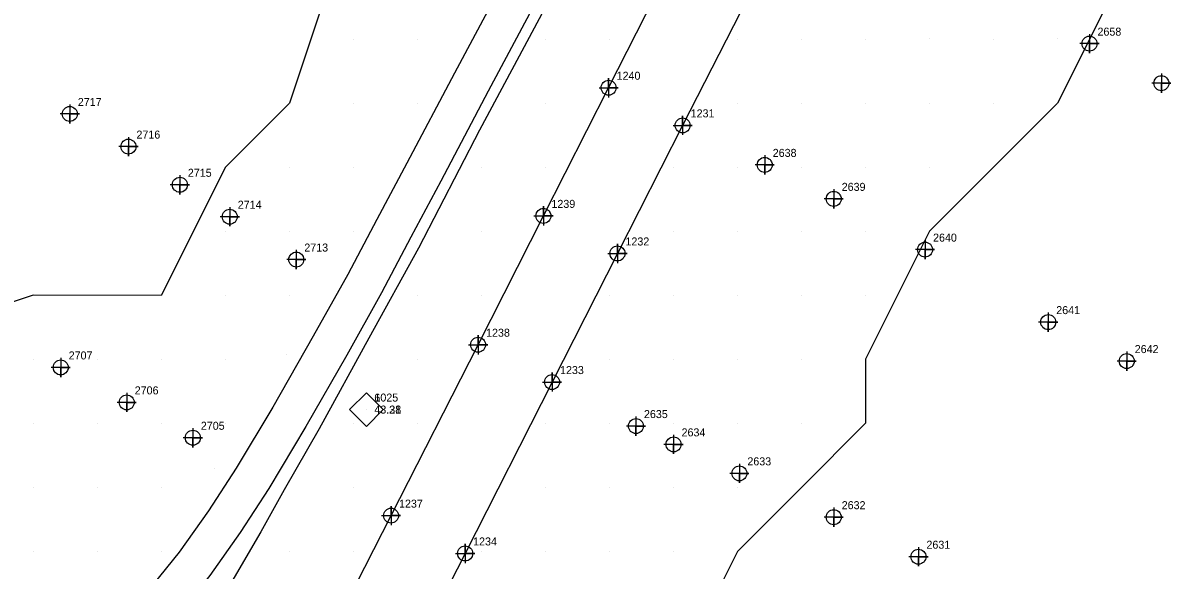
# Model space of a CAD drawing. Extents: x 2062781 to 2066835, y 358981 to 366501.
# Drawn here: x 2064535.6 to 2064893.4, y 362613.9 to 362784.8 of the extents above; entities that cross this region are included whole.
import ezdxf

# ---------------------------------------------------------------- set-up
doc = ezdxf.new("R2010")
doc.units = 0
for name, color, linetype in [('COGO Default Point Elevation', 7, 'Continuous'), ('COGO Default Point Number', 7, 'Continuous'), ('CTL Supplemental Horizontal and Vertical CELL', 7, 'Continuous'), ('CTL Supplemental Horizontal and Vertical Cogo Elevation', 7, 'Continuous'), ('CTL Supplemental Horizontal and Vertical Cogo Number', 7, 'Continuous'), ('Exist DTM Regular Point CELL', 7, 'Continuous'), ('Exist DTM Regular Point Cogo Number', 7, 'Continuous'), ('Exist Structure Major Deck Tunnel Box Culvert', 7, 'Continuous'), ('Exist Structure Major Deck Tunnel Box Culvert Cogo Number', 7, 'Continuous'), ('Exist Structure Major Deck Tunnel Box Culvert Cogo Point CELL', 7, 'Continuous'), ('PH Exist DTM Breakline', 7, 'Continuous'), ('PH Exist DTM Point', 7, 'Continuous')]:
    doc.layers.add(name, color=color, linetype=linetype)

msp = doc.modelspace()

# ---------------------------------------------------------------- linework, layer by layer
at = {"layer": 'CTL Supplemental Horizontal and Vertical CELL'}
msp.add_line((2064642.89, 362664.04), (2064642.89, 362664.04), dxfattribs=at)
msp.add_lwpolyline([(2064637.67, 362664.06), (2064642.91, 362669.3), (2064648.16, 362664.05), (2064642.92, 362658.81)], close=True, dxfattribs=at)
at = {"layer": 'Exist DTM Regular Point CELL'}
for points in [[(2064868.83, 362781.36), (2064868.83, 362775.36), (2064868.83, 362778.36), (2064871.83, 362778.36), (2064865.83, 362778.36)], [(2064891.28, 362769.01), (2064891.28, 362763.01), (2064891.28, 362766.01), (2064894.28, 362766.01), (2064888.28, 362766.01)], [(2064550.27, 362759.39), (2064550.27, 362753.39), (2064550.27, 362756.39), (2064553.27, 362756.39), (2064547.27, 362756.39)], [(2064568.59, 362749.2), (2064568.59, 362743.2), (2064568.59, 362746.2), (2064571.59, 362746.2), (2064565.59, 362746.2)], [(2064767.37, 362743.49), (2064767.37, 362737.49), (2064767.37, 362740.49), (2064770.37, 362740.49), (2064764.37, 362740.49)], [(2064584.65, 362737.28), (2064584.65, 362731.28), (2064584.65, 362734.28), (2064587.65, 362734.28), (2064581.65, 362734.28)], [(2064788.92, 362732.88), (2064788.92, 362726.88), (2064788.92, 362729.88), (2064791.92, 362729.88), (2064785.92, 362729.88)], [(2064600.24, 362727.3), (2064600.24, 362721.3), (2064600.24, 362724.3), (2064603.24, 362724.3), (2064597.24, 362724.3)], [(2064817.46, 362717.02), (2064817.46, 362711.02), (2064817.46, 362714.02), (2064820.46, 362714.02), (2064814.46, 362714.02)], [(2064621.03, 362713.92), (2064621.03, 362707.92), (2064621.03, 362710.92), (2064624.03, 362710.92), (2064618.03, 362710.92)], [(2064855.94, 362694.37), (2064855.94, 362688.37), (2064855.94, 362691.37), (2064858.94, 362691.37), (2064852.94, 362691.37)], [(2064547.42, 362680.22), (2064547.42, 362674.22), (2064547.42, 362677.22), (2064550.42, 362677.22), (2064544.42, 362677.22)], [(2064880.46, 362682.2), (2064880.46, 362676.2), (2064880.46, 362679.2), (2064883.46, 362679.2), (2064877.46, 362679.2)], [(2064568.05, 362669.3), (2064568.05, 362663.3), (2064568.05, 362666.3), (2064571.05, 362666.3), (2064565.05, 362666.3)], [(2064727.14, 362661.9), (2064727.14, 362655.9), (2064727.14, 362658.9), (2064730.14, 362658.9), (2064724.14, 362658.9)], [(2064588.71, 362658.25), (2064588.71, 362652.25), (2064588.71, 362655.25), (2064591.71, 362655.25), (2064585.71, 362655.25)], [(2064738.89, 362656.18), (2064738.89, 362650.18), (2064738.89, 362653.18), (2064741.89, 362653.18), (2064735.89, 362653.18)], [(2064759.45, 362647.13), (2064759.45, 362641.13), (2064759.45, 362644.13), (2064762.45, 362644.13), (2064756.45, 362644.13)], [(2064788.92, 362633.44), (2064788.92, 362627.44), (2064788.92, 362630.44), (2064791.92, 362630.44), (2064785.92, 362630.44)], [(2064815.39, 362621.09), (2064815.39, 362615.09), (2064815.39, 362618.09), (2064818.39, 362618.09), (2064812.39, 362618.09)]]:
    msp.add_lwpolyline(points, dxfattribs=at)
for centre in [(2064868.83, 362778.36), (2064891.28, 362766.01), (2064550.27, 362756.39), (2064568.59, 362746.2), (2064767.37, 362740.49), (2064584.65, 362734.28), (2064788.92, 362729.88), (2064600.24, 362724.3), (2064817.46, 362714.02), (2064621.03, 362710.92), (2064855.94, 362691.37), (2064547.42, 362677.22), (2064880.46, 362679.2), (2064568.05, 362666.3), (2064727.14, 362658.9), (2064588.71, 362655.25), (2064738.89, 362653.18), (2064759.45, 362644.13), (2064788.92, 362630.44), (2064815.39, 362618.09)]:
    msp.add_circle(centre, 2.34, dxfattribs=at)
at = {"layer": 'Exist Structure Major Deck Tunnel Box Culvert'}
for points in [[(2064623.4, 362577.44), (2064650.62, 362630.92), (2064677.82, 362684.31), (2064698.23, 362724.56), (2064718.6, 362764.59), (2064738.99, 362804.71), (2064759.36, 362844.81), (2064779.84, 362884.94), (2064800.12, 362924.98), (2064820.56, 362965.07), (2064840.94, 363005.22), (2064861.36, 363045.25), (2064881.68, 363085.34), (2064902.1, 363125.46), (2064922.64, 363165.68)], [(2064945.77, 363153.79), (2064925.42, 363113.93), (2064904.9, 363073.71), (2064884.54, 363033.52), (2064864.2, 362993.6), (2064843.79, 362953.32), (2064823.4, 362913.38), (2064803.04, 362873.21), (2064782.63, 362833.19), (2064762.2, 362793.01), (2064741.73, 362752.83), (2064721.36, 362712.82), (2064700.92, 362672.65), (2064673.77, 362619.11), (2064646.54, 362565.66)]]:
    msp.add_lwpolyline(points, dxfattribs=at)
at = {"layer": 'Exist Structure Major Deck Tunnel Box Culvert Cogo Point CELL'}
for points in [[(2064715.6, 362764.59), (2064721.6, 362764.59), (2064718.6, 362764.59), (2064718.6, 362767.59), (2064718.6, 362761.59)], [(2064715.6, 362764.59), (2064721.6, 362764.59), (2064718.6, 362764.59), (2064718.6, 362767.59), (2064718.6, 362761.59)], [(2064715.6, 362764.59), (2064721.6, 362764.59), (2064718.6, 362764.59), (2064718.6, 362767.59), (2064718.6, 362761.59)], [(2064738.73, 362752.83), (2064744.73, 362752.83), (2064741.73, 362752.83), (2064741.73, 362755.83), (2064741.73, 362749.83)], [(2064738.73, 362752.83), (2064744.73, 362752.83), (2064741.73, 362752.83), (2064741.73, 362755.83), (2064741.73, 362749.83)], [(2064738.73, 362752.83), (2064744.73, 362752.83), (2064741.73, 362752.83), (2064741.73, 362755.83), (2064741.73, 362749.83)], [(2064695.23, 362724.56), (2064701.23, 362724.56), (2064698.23, 362724.56), (2064698.23, 362727.56), (2064698.23, 362721.56)], [(2064695.23, 362724.56), (2064701.23, 362724.56), (2064698.23, 362724.56), (2064698.23, 362727.56), (2064698.23, 362721.56)], [(2064695.23, 362724.56), (2064701.23, 362724.56), (2064698.23, 362724.56), (2064698.23, 362727.56), (2064698.23, 362721.56)], [(2064718.36, 362712.82), (2064724.36, 362712.82), (2064721.36, 362712.82), (2064721.36, 362715.82), (2064721.36, 362709.82)], [(2064718.36, 362712.82), (2064724.36, 362712.82), (2064721.36, 362712.82), (2064721.36, 362715.82), (2064721.36, 362709.82)], [(2064718.36, 362712.82), (2064724.36, 362712.82), (2064721.36, 362712.82), (2064721.36, 362715.82), (2064721.36, 362709.82)], [(2064674.82, 362684.31), (2064680.82, 362684.31), (2064677.82, 362684.31), (2064677.82, 362687.31), (2064677.82, 362681.31)], [(2064674.82, 362684.31), (2064680.82, 362684.31), (2064677.82, 362684.31), (2064677.82, 362687.31), (2064677.82, 362681.31)], [(2064674.82, 362684.31), (2064680.82, 362684.31), (2064677.82, 362684.31), (2064677.82, 362687.31), (2064677.82, 362681.31)], [(2064697.92, 362672.65), (2064703.92, 362672.65), (2064700.92, 362672.65), (2064700.92, 362675.65), (2064700.92, 362669.65)], [(2064697.92, 362672.65), (2064703.92, 362672.65), (2064700.92, 362672.65), (2064700.92, 362675.65), (2064700.92, 362669.65)], [(2064697.92, 362672.65), (2064703.92, 362672.65), (2064700.92, 362672.65), (2064700.92, 362675.65), (2064700.92, 362669.65)], [(2064647.62, 362630.92), (2064653.62, 362630.92), (2064650.62, 362630.92), (2064650.62, 362633.92), (2064650.62, 362627.92)], [(2064647.62, 362630.92), (2064653.62, 362630.92), (2064650.62, 362630.92), (2064650.62, 362633.92), (2064650.62, 362627.92)], [(2064647.62, 362630.92), (2064653.62, 362630.92), (2064650.62, 362630.92), (2064650.62, 362633.92), (2064650.62, 362627.92)], [(2064670.77, 362619.11), (2064676.77, 362619.11), (2064673.77, 362619.11), (2064673.77, 362622.11), (2064673.77, 362616.11)], [(2064670.77, 362619.11), (2064676.77, 362619.11), (2064673.77, 362619.11), (2064673.77, 362622.11), (2064673.77, 362616.11)], [(2064670.77, 362619.11), (2064676.77, 362619.11), (2064673.77, 362619.11), (2064673.77, 362622.11), (2064673.77, 362616.11)]]:
    msp.add_lwpolyline(points, dxfattribs=at)
for centre in [(2064718.6, 362764.59), (2064718.6, 362764.59), (2064718.6, 362764.59), (2064741.73, 362752.83), (2064741.73, 362752.83), (2064741.73, 362752.83), (2064698.23, 362724.56), (2064698.23, 362724.56), (2064698.23, 362724.56), (2064721.36, 362712.82), (2064721.36, 362712.82), (2064721.36, 362712.82), (2064677.82, 362684.31), (2064677.82, 362684.31), (2064677.82, 362684.31), (2064700.92, 362672.65), (2064700.92, 362672.65), (2064700.92, 362672.65), (2064650.62, 362630.92), (2064650.62, 362630.92), (2064650.62, 362630.92), (2064673.77, 362619.11), (2064673.77, 362619.11), (2064673.77, 362619.11)]:
    msp.add_circle(centre, 2.34, dxfattribs=at)
at = {"layer": 'PH Exist DTM Breakline'}
for points in [[(2064807.3, 363030.11), (2064802.32, 363011.11), (2064797.84, 362995.47), (2064791.78, 362977.67), (2064781.44, 362953.56), (2064768.13, 362924.72), (2064754.4, 362897.09), (2064735.4, 362860.89), (2064708.55, 362807.94), (2064678.24, 362751.31), (2064659.16, 362714.52), (2064643.7, 362686.38), (2064628.13, 362658.09), (2064617.21, 362639.02), (2064609.98, 362625.86), (2064598.02, 362605.33), (2064591.98, 362596.35), (2064587.07, 362588.82), (2064583.37, 362583.25)], [(2064785.71, 363007.19), (2064779.45, 362990.06), (2064772.48, 362972.75), (2064765.86, 362956.39), (2064759.45, 362942.62), (2064749.79, 362923.28), (2064738.37, 362900.81), (2064726.23, 362876.54), (2064713.46, 362852.12), (2064699.51, 362825.61), (2064684.05, 362794.78), (2064670.4, 362769.18), (2064655.54, 362741.04), (2064646.23, 362723.48), (2064637.14, 362706.29), (2064626.33, 362686.94), (2064613.68, 362664.82), (2064602.29, 362645.78), (2064593.55, 362632.4), (2064584.44, 362619.51), (2064571.75, 362603.76), (2064561.33, 362592.06)], [(2064797.04, 363003.22), (2064790.66, 362985.76), (2064783.61, 362968.25), (2064776.87, 362951.61), (2064770.26, 362937.41), (2064760.51, 362917.88), (2064749.09, 362895.41), (2064736.91, 362871.07), (2064724.09, 362846.54), (2064710.18, 362820.13), (2064694.71, 362789.26), (2064681, 362763.56), (2064666.15, 362735.42), (2064656.83, 362717.87), (2064647.69, 362700.56), (2064636.78, 362681.03), (2064624.04, 362658.76), (2064612.46, 362639.42), (2064603.47, 362625.65), (2064594.02, 362612.27), (2064580.91, 362596.01), (2064570.29, 362584.08)], [(2064709.63, 362950.09), (2064707.87, 362925.16), (2064698.86, 362899.76), (2064684.28, 362855.7), (2064658.86, 362839.76), (2064638.86, 362819.76), (2064618.86, 362759.76), (2064598.86, 362739.76), (2064578.84, 362699.72), (2064538.86, 362699.76), (2064478.86, 362679.76), (2064478.93, 362700.07), (2064458.86, 362739.76), (2064438.86, 362739.76), (2064418.86, 362739.76), (2064393.6, 362752.5)], [(2064938.86, 362939.76), (2064898.86, 362919.76), (2064878.86, 362899.76), (2064858.86, 362859.76), (2064878.86, 362839.76), (2064878.86, 362819.76), (2064878.86, 362799.76), (2064858.86, 362759.76), (2064838.86, 362739.76), (2064818.86, 362719.76), (2064798.86, 362679.76), (2064798.86, 362659.76), (2064778.86, 362639.76), (2064758.86, 362619.76), (2064738.86, 362579.76), (2064738.86, 362559.76), (2064738.86, 362539.76), (2064738.86, 362519.76), (2064738.6, 362499.33), (2064738.86, 362479.76), (2064718.86, 362459.76), (2064698.86, 362459.76), (2064658.86, 362419.76)]]:
    msp.add_lwpolyline(points, dxfattribs=at)
at = {"layer": 'PH Exist DTM Point'}
for p, q in [((2064638.86, 362779.76), (2064638.86, 362779.76)), ((2064658.86, 362779.76), (2064658.86, 362779.76)), ((2064698.86, 362779.76), (2064698.86, 362779.76)), ((2064718.86, 362779.76), (2064718.86, 362779.76)), ((2064758.86, 362779.76), (2064758.86, 362779.76)), ((2064778.86, 362779.76), (2064778.86, 362779.76)), ((2064798.86, 362779.76), (2064798.86, 362779.76)), ((2064818.84, 362779.9), (2064818.84, 362779.9)), ((2064838.86, 362779.76), (2064838.86, 362779.76)), ((2064858.75, 362779.9), (2064858.75, 362779.9)), ((2064638.86, 362759.76), (2064638.86, 362759.76)), ((2064658.86, 362759.76), (2064658.86, 362759.76)), ((2064698.86, 362759.76), (2064698.86, 362759.76)), ((2064758.86, 362759.76), (2064758.86, 362759.76)), ((2064778.86, 362759.76), (2064778.86, 362759.76)), ((2064798.86, 362759.76), (2064798.86, 362759.76)), ((2064818.86, 362759.76), (2064818.86, 362759.76)), ((2064838.86, 362759.76), (2064838.86, 362759.76)), ((2064618.86, 362739.76), (2064618.86, 362739.76)), ((2064638.86, 362739.76), (2064638.86, 362739.76)), ((2064678.86, 362739.76), (2064678.86, 362739.76)), ((2064698.86, 362739.76), (2064698.86, 362739.76)), ((2064738.86, 362739.76), (2064738.86, 362739.76)), ((2064758.86, 362739.76), (2064758.86, 362739.76)), ((2064778.86, 362739.76), (2064778.86, 362739.76)), ((2064798.86, 362739.76), (2064798.86, 362739.76)), ((2064818.86, 362739.76), (2064818.86, 362739.76)), ((2064598.86, 362719.76), (2064598.86, 362719.76)), ((2064618.86, 362719.76), (2064618.86, 362719.76)), ((2064638.86, 362719.76), (2064638.86, 362719.76)), ((2064678.86, 362719.76), (2064678.86, 362719.76)), ((2064738.86, 362719.76), (2064738.86, 362719.76)), ((2064758.86, 362719.76), (2064758.86, 362719.76)), ((2064778.86, 362719.76), (2064778.86, 362719.76)), ((2064798.86, 362719.76), (2064798.86, 362719.76)), ((2064598.86, 362699.76), (2064598.86, 362699.76)), ((2064618.86, 362699.76), (2064618.86, 362699.76)), ((2064658.82, 362699.78), (2064658.82, 362699.78)), ((2064678.86, 362699.76), (2064678.86, 362699.76)), ((2064718.86, 362699.76), (2064718.86, 362699.76)), ((2064738.86, 362699.76), (2064738.86, 362699.76)), ((2064758.86, 362699.76), (2064758.86, 362699.76)), ((2064778.86, 362699.76), (2064778.86, 362699.76)), ((2064798.86, 362699.76), (2064798.86, 362699.76)), ((2064538.86, 362679.76), (2064538.86, 362679.76)), ((2064558.86, 362679.76), (2064558.86, 362679.76)), ((2064578.86, 362679.76), (2064578.86, 362679.76)), ((2064598.86, 362679.76), (2064598.86, 362679.76)), ((2064617.98, 362681.33), (2064617.98, 362681.33)), ((2064658.86, 362679.76), (2064658.86, 362679.76)), ((2064718.86, 362679.76), (2064718.86, 362679.76)), ((2064738.86, 362679.76), (2064738.86, 362679.76)), ((2064758.86, 362679.76), (2064758.86, 362679.76)), ((2064778.86, 362679.76), (2064778.86, 362679.76)), ((2064538.86, 362659.76), (2064538.86, 362659.76)), ((2064558.82, 362659.78), (2064558.82, 362659.78)), ((2064578.87, 362659.79), (2064578.87, 362659.79)), ((2064598.86, 362659.76), (2064598.86, 362659.76)), ((2064638.86, 362659.76), (2064638.86, 362659.76)), ((2064658.86, 362659.76), (2064658.86, 362659.76)), ((2064698.86, 362659.76), (2064698.86, 362659.76)), ((2064718.86, 362659.76), (2064718.86, 362659.76)), ((2064738.86, 362659.76), (2064738.86, 362659.76)), ((2064758.86, 362659.76), (2064758.86, 362659.76)), ((2064778.86, 362659.76), (2064778.86, 362659.76)), ((2064595.61, 362645.72), (2064595.61, 362645.72)), ((2064538.86, 362639.76), (2064538.86, 362639.76)), ((2064558.86, 362639.76), (2064558.86, 362639.76)), ((2064578.86, 362639.76), (2064578.86, 362639.76)), ((2064638.86, 362639.76), (2064638.86, 362639.76)), ((2064698.86, 362639.76), (2064698.86, 362639.76)), ((2064718.89, 362639.74), (2064718.89, 362639.74)), ((2064738.86, 362639.76), (2064738.86, 362639.76)), ((2064758.86, 362639.76), (2064758.86, 362639.76)), ((2064538.86, 362619.76), (2064538.86, 362619.76)), ((2064558.86, 362619.76), (2064558.86, 362619.76)), ((2064578.86, 362619.76), (2064578.86, 362619.76)), ((2064618.86, 362619.76), (2064618.86, 362619.76)), ((2064638.86, 362619.76), (2064638.86, 362619.76)), ((2064678.86, 362619.76), (2064678.86, 362619.76)), ((2064698.86, 362619.76), (2064698.86, 362619.76)), ((2064718.86, 362619.76), (2064718.86, 362619.76)), ((2064738.86, 362619.76), (2064738.86, 362619.76))]:
    msp.add_line(p, q, dxfattribs=at)

# ---------------------------------------------------------------- texts
at = {"layer": 'COGO Default Point Elevation'}
msp.add_text('43.28', height=2.5, dxfattribs=at).set_placement((2064645.43, 362662.81))
at = {"layer": 'COGO Default Point Number'}
msp.add_text('1025', height=2.5, dxfattribs=at).set_placement((2064645.43, 362666.56))
at = {"layer": 'CTL Supplemental Horizontal and Vertical Cogo Elevation'}
msp.add_text('43.31', height=2.5, dxfattribs=at).set_placement((2064645.39, 362662.79))
at = {"layer": 'CTL Supplemental Horizontal and Vertical Cogo Number'}
msp.add_text('6', height=2.5, dxfattribs=at).set_placement((2064645.39, 362666.54))
at = {"layer": 'Exist DTM Regular Point Cogo Number'}
for s, p in [('2658', (2064871.33, 362780.86)), ('2658', (2064871.33, 362780.86)), ('2658', (2064871.33, 362780.86)), ('2717', (2064552.77, 362758.89)), ('2717', (2064552.77, 362758.89)), ('2717', (2064552.77, 362758.89)), ('2716', (2064571.09, 362748.7)), ('2716', (2064571.09, 362748.7)), ('2716', (2064571.09, 362748.7)), ('2638', (2064769.87, 362742.99)), ('2638', (2064769.87, 362742.99)), ('2638', (2064769.87, 362742.99)), ('2715', (2064587.15, 362736.78)), ('2715', (2064587.15, 362736.78)), ('2715', (2064587.15, 362736.78)), ('2639', (2064791.42, 362732.38)), ('2639', (2064791.42, 362732.38)), ('2639', (2064791.42, 362732.38)), ('2714', (2064602.74, 362726.8)), ('2714', (2064602.74, 362726.8)), ('2714', (2064602.74, 362726.8)), ('2640', (2064819.96, 362716.52)), ('2640', (2064819.96, 362716.52)), ('2640', (2064819.96, 362716.52)), ('2713', (2064623.53, 362713.42)), ('2713', (2064623.53, 362713.42)), ('2713', (2064623.53, 362713.42)), ('2641', (2064858.44, 362693.87)), ('2641', (2064858.44, 362693.87)), ('2641', (2064858.44, 362693.87)), ('2642', (2064882.96, 362681.7)), ('2642', (2064882.96, 362681.7)), ('2642', (2064882.96, 362681.7)), ('2707', (2064549.92, 362679.72)), ('2707', (2064549.92, 362679.72)), ('2707', (2064549.92, 362679.72)), ('2706', (2064570.55, 362668.8)), ('2706', (2064570.55, 362668.8)), ('2706', (2064570.55, 362668.8)), ('2635', (2064729.64, 362661.4)), ('2635', (2064729.64, 362661.4)), ('2635', (2064729.64, 362661.4)), ('2705', (2064591.21, 362657.75)), ('2705', (2064591.21, 362657.75)), ('2705', (2064591.21, 362657.75)), ('2634', (2064741.39, 362655.68)), ('2634', (2064741.39, 362655.68)), ('2634', (2064741.39, 362655.68)), ('2633', (2064761.95, 362646.63)), ('2633', (2064761.95, 362646.63)), ('2633', (2064761.95, 362646.63)), ('2632', (2064791.42, 362632.94)), ('2632', (2064791.42, 362632.94)), ('2632', (2064791.42, 362632.94)), ('2631', (2064817.89, 362620.59)), ('2631', (2064817.89, 362620.59)), ('2631', (2064817.89, 362620.59))]:
    msp.add_text(s, height=2.5, dxfattribs=at).set_placement(p)
at = {"layer": 'Exist Structure Major Deck Tunnel Box Culvert Cogo Number'}
for s, p in [('1240', (2064721.1, 362767.09)), ('1240', (2064721.1, 362767.09)), ('1240', (2064721.1, 362767.09)), ('1231', (2064744.23, 362755.33)), ('1231', (2064744.23, 362755.33)), ('1231', (2064744.23, 362755.33)), ('1239', (2064700.73, 362727.06)), ('1239', (2064700.73, 362727.06)), ('1239', (2064700.73, 362727.06)), ('1232', (2064723.86, 362715.32)), ('1232', (2064723.86, 362715.32)), ('1232', (2064723.86, 362715.32)), ('1238', (2064680.32, 362686.81)), ('1238', (2064680.32, 362686.81)), ('1238', (2064680.32, 362686.81)), ('1233', (2064703.42, 362675.15)), ('1233', (2064703.42, 362675.15)), ('1233', (2064703.42, 362675.15)), ('1237', (2064653.12, 362633.42)), ('1237', (2064653.12, 362633.42)), ('1237', (2064653.12, 362633.42)), ('1234', (2064676.27, 362621.61)), ('1234', (2064676.27, 362621.61)), ('1234', (2064676.27, 362621.61))]:
    msp.add_text(s, height=2.5, dxfattribs=at).set_placement(p)

doc.saveas('drawing.dxf')
